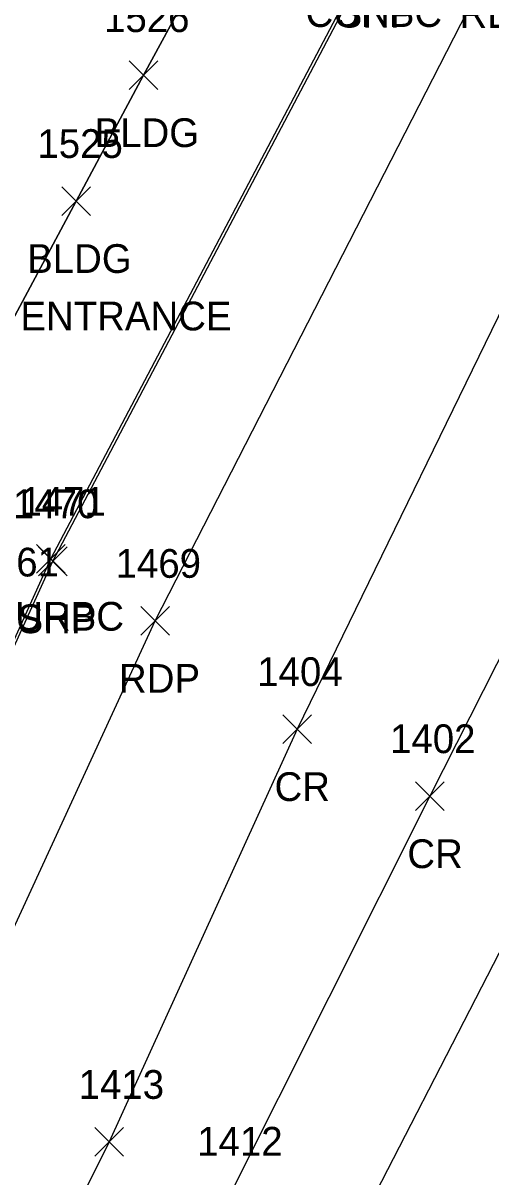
# Model space of a CAD drawing. Extents: x 1462668 to 1465147, y 550359 to 557351.
# Drawn here: x 1464628.9 to 1464661.4, y 552550.9 to 552631.2 of the extents above; entities that cross this region are included whole.
import ezdxf

# ---------------------------------------------------------------- set-up
doc = ezdxf.new("R2010")
doc.units = 0
for name, color, linetype in [('L_A', 7, 'Continuous'), ('L_C', 7, 'Continuous'), ('L_I', 7, 'Continuous'), ('L_TIC', 7, 'Continuous'), ('LBC', 7, 'Continuous'), ('Level 6', 7, 'Continuous'), ('P_A', 7, 'Continuous'), ('P_I', 7, 'Continuous'), ('P_TIC', 7, 'Continuous'), ('PET', 7, 'Continuous'), ('PRC', 7, 'Continuous'), ('PSP', 7, 'Continuous'), ('R_A', 7, 'Continuous'), ('R_I', 7, 'Continuous'), ('R_TIC', 7, 'Continuous'), ('RC', 7, 'Continuous'), ('U_I', 7, 'Continuous')]:
    doc.layers.add(name, color=color, linetype=linetype)

msp = doc.modelspace()

# ---------------------------------------------------------------- linework, layer by layer
at = {"layer": 'L_TIC'}
for points in [[(1464636.245, 552626.541), (1464638.245, 552628.541)], [(1464638.245, 552626.541), (1464636.245, 552628.541)], [(1464631.549, 552617.783), (1464633.549, 552619.783)], [(1464633.549, 552617.783), (1464631.549, 552619.783)]]:
    msp.add_lwpolyline(points, dxfattribs=at)
at = {"layer": 'LBC'}
for points in [[(1464637.245, 552627.541), (1464646.653, 552644.839)], [(1464623.259, 552601.463), (1464632.549, 552618.783), (1464637.245, 552627.541)]]:
    msp.add_lwpolyline(points, dxfattribs=at)
at = {"layer": 'Level 6'}
msp.add_lwpolyline([(1464646.653, 552644.839), (1464637.245, 552627.541), (1464632.549, 552618.783), (1464623.259, 552601.463)], dxfattribs=at)
at = {"layer": 'P_TIC'}
for points in [[(1464629.936, 552592.717), (1464631.936, 552594.717)], [(1464631.936, 552592.717), (1464629.936, 552594.717)], [(1464637.05, 552588.571), (1464639.05, 552590.571)], [(1464639.05, 552588.571), (1464637.05, 552590.571)], [(1464646.939, 552581.04), (1464648.939, 552583.04)], [(1464648.939, 552581.04), (1464646.939, 552583.04)], [(1464656.19, 552576.372), (1464658.19, 552578.372)], [(1464658.19, 552576.372), (1464656.19, 552578.372)], [(1464633.853, 552552.318), (1464635.853, 552554.318)], [(1464635.853, 552552.318), (1464633.853, 552554.318)]]:
    msp.add_lwpolyline(points, dxfattribs=at)
at = {"layer": 'PET'}
for points in [[(1464572.057, 552448.49), (1464578.391, 552461.448), (1464597.777, 552501.888), (1464609.96, 552527.834), (1464625.745, 552562.93), (1464638.05, 552589.571), (1464661.765, 552635.83), (1464669.488, 552648.306)], [(1464688.812, 552609.874), (1464680.611, 552601.191), (1464673.858, 552589.463), (1464650.971, 552545.028), (1464631.533, 552508.126), (1464616.104, 552478.119), (1464603.71, 552453.411)]]:
    msp.add_lwpolyline(points, dxfattribs=at)
at = {"layer": 'PRC'}
for points in [[(1464682.067, 552623.831), (1464670.226, 552603.072), (1464657.19, 552577.372), (1464643.112, 552549.366), (1464624.394, 552512.893)], [(1464665.112, 552617.199), (1464647.939, 552582.04), (1464634.853, 552553.318), (1464610.757, 552505.159), (1464598.841, 552479.239), (1464581.961, 552444.147)]]:
    msp.add_lwpolyline(points, dxfattribs=at)
at = {"layer": 'PSP'}
msp.add_lwpolyline([(1464566.349, 552450.844), (1464572.204, 552463.839), (1464577.981, 552476.641), (1464591.937, 552507.348), (1464602.33, 552530.894), (1464618.432, 552566.275), (1464630.936, 552593.717), (1464653.16, 552635.856), (1464653.539, 552639.257)], dxfattribs=at)
at = {"layer": 'R_TIC'}
for points in [[(1464629.793, 552592.891), (1464631.793, 552594.891)], [(1464631.793, 552592.891), (1464629.793, 552594.891)]]:
    msp.add_lwpolyline(points, dxfattribs=at)
at = {"layer": 'RC'}
msp.add_lwpolyline([(1464566.263, 552450.941), (1464572.133, 552463.791), (1464576.159, 552473.046), (1464577.831, 552476.683), (1464591.724, 552507.478), (1464602.034, 552530.955), (1464618.293, 552566.346), (1464630.793, 552593.891), (1464652.949, 552635.897), (1464653.453, 552639.165), (1464652.019, 552641.301), (1464646.653, 552644.839)], dxfattribs=at)

# ---------------------------------------------------------------- texts
at = {"layer": 'L_A'}
for p in [(1464633.835, 552622.541), (1464629.139, 552613.783)]:
    msp.add_text('BLDG', height=2, dxfattribs=at).set_placement(p)
at = {"layer": 'L_C'}
msp.add_text('BANK ENTRANCE', height=2, dxfattribs=at).set_placement((1464620.643, 552609.783))
at = {"layer": 'L_I'}
for s, p in [('1526', (1464634.497, 552630.541)), ('1525', (1464629.856, 552621.783))]:
    msp.add_text(s, height=2, dxfattribs=at).set_placement(p)
at = {"layer": 'P_A'}
for s, p in [('SHP', (1464650.696, 552630.856)), ('RDP', (1464659.253, 552630.83)), ('SHP', (1464628.471, 552588.717)), ('RDP', (1464635.538, 552584.571)), ('CR', (1464646.372, 552577.04)), ('CR', (1464655.623, 552572.372))]:
    msp.add_text(s, height=2, dxfattribs=at).set_placement(p)
at = {"layer": 'P_I'}
for s, p in [('1470', (1464628.156, 552596.717)), ('1469', (1464635.301, 552592.571)), ('1404', (1464645.167, 552585.04)), ('1402', (1464654.418, 552580.372)), ('1413', (1464632.727, 552556.318)), ('1412', (1464640.986, 552552.366))]:
    msp.add_text(s, height=2, dxfattribs=at).set_placement(p)
at = {"layer": 'R_A'}
for p in [(1464648.532, 552630.897), (1464626.376, 552588.891)]:
    msp.add_text('CURBC', height=2, dxfattribs=at).set_placement(p)
at = {"layer": 'R_I'}
msp.add_text('1471', height=2, dxfattribs=at).set_placement((1464628.667, 552596.891))
at = {"layer": 'U_I'}
msp.add_text('1561', height=2, dxfattribs=at).set_placement((1464625.405, 552592.663))

doc.saveas('drawing.dxf')
